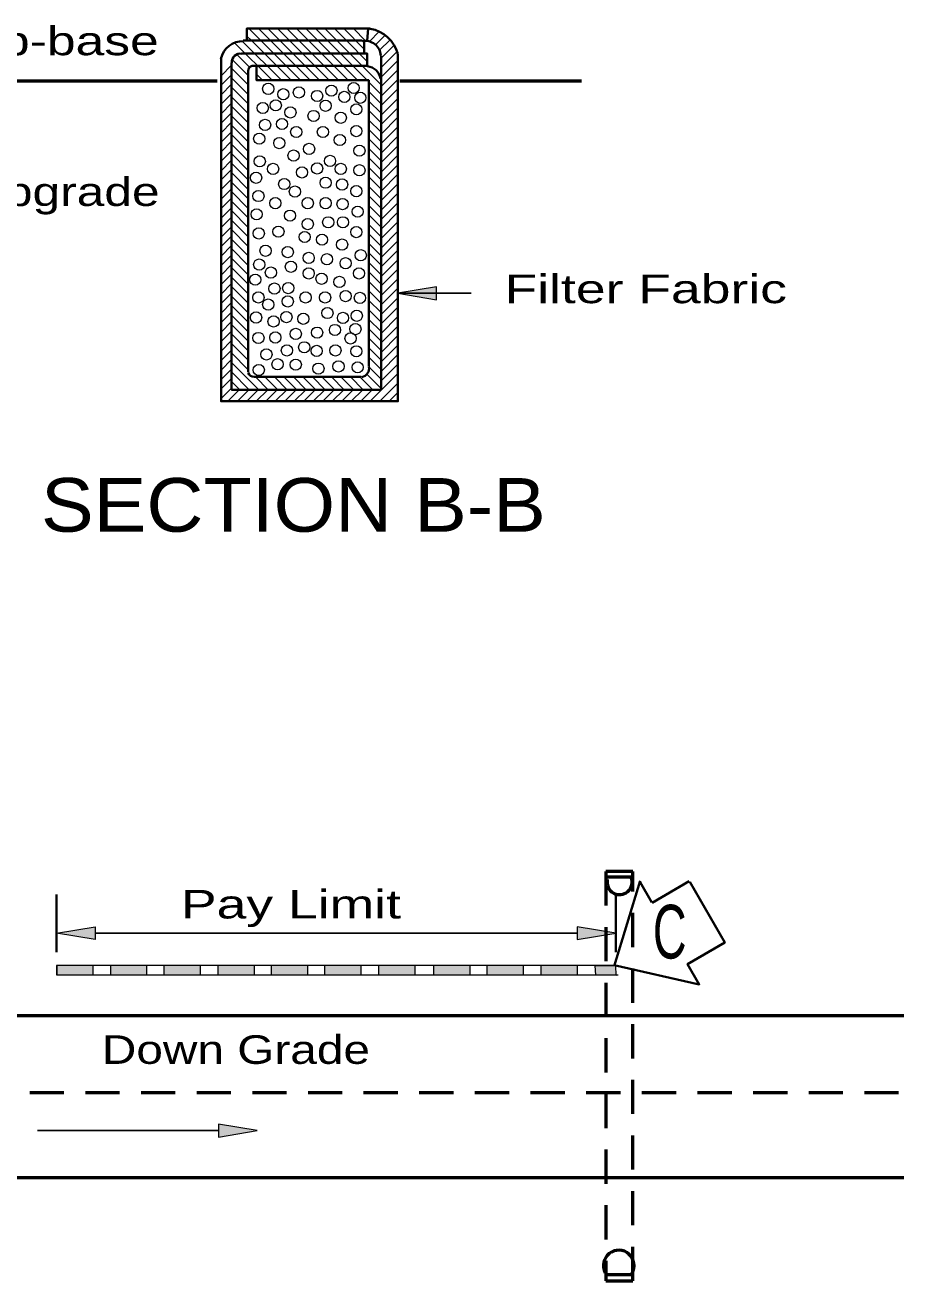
# Model space of a CAD drawing. Extents: x 36 to 71.3, y 0.3 to 22.3.
# Drawn here: x 45.78 to 49.87, y 10.83 to 16.68 of the extents above; entities that cross this region are included whole.
import ezdxf

# ---------------------------------------------------------------- set-up
doc = ezdxf.new("R2010")
doc.units = 0
doc.header["$LTSCALE"] = 0.053
doc.linetypes.add('MEDIUM_DASHED', pattern=[4.5, 3, -1.5])
for name, color, linetype, lineweight in [('1', 7, 'Continuous', 13), ('2', 7, 'Continuous', 13), ('3', 7, 'MEDIUM_DASHED', 53), ('4', 7, 'Continuous', 13)]:
    doc.layers.add(name, color=color, linetype=linetype, lineweight=lineweight)

msp = doc.modelspace()

# ---------------------------------------------------------------- hatches: boundary and pattern name
at = {"layer": '1'}
for points in [[(46.10875, 12.48133), (46.10875, 12.42133), (45.92875, 12.45133), (45.92875, 12.45133)], [(48.35158, 12.48133), (48.35158, 12.42133), (48.53158, 12.45133), (48.53158, 12.45133)], [(45.92875, 12.25708), (46.09933, 12.25708), (46.09933, 12.30033), (45.92875, 12.30033)], [(46.17933, 12.25708), (46.34992, 12.25708), (46.34992, 12.30033), (46.17933, 12.30033)], [(46.42783, 12.25708), (46.59842, 12.25708), (46.59842, 12.30033), (46.42783, 12.30033)], [(46.6795, 12.25708), (46.85008, 12.25708), (46.85008, 12.30033), (46.6795, 12.30033)], [(46.928, 12.25708), (47.09858, 12.25708), (47.09858, 12.30033), (46.928, 12.30033)], [(47.1765, 12.25708), (47.347, 12.25708), (47.347, 12.30033), (47.1765, 12.30033)], [(47.42808, 12.25708), (47.59867, 12.25708), (47.59867, 12.30033), (47.42808, 12.30033)], [(47.68292, 12.25708), (47.8535, 12.25708), (47.8535, 12.30033), (47.68292, 12.30033)], [(47.93142, 12.25708), (48.102, 12.25708), (48.102, 12.30033), (47.93142, 12.30033)], [(48.18308, 12.25708), (48.35358, 12.25708), (48.35358, 12.30033), (48.18308, 12.30033)], [(48.43683, 12.25708), (48.53367, 12.25633), (48.53158, 12.2995), (48.43467, 12.2995)]]:
    msp.add_hatch(color=256, dxfattribs=at).paths.add_polyline_path(points)
at = {"layer": '2'}
for points in [[(47.69758, 15.40008), (47.69758, 15.46008), (47.51758, 15.43008), (47.51758, 15.43008)], [(46.68267, 11.56167), (46.68267, 11.50167), (46.86267, 11.53167), (46.86267, 11.53167)]]:
    msp.add_hatch(color=256, dxfattribs=at).paths.add_polyline_path(points)

# ---------------------------------------------------------------- linework, layer by layer
at = {"layer": '1'}
for p, q in [((46.97633, 16.42192), (46.7935, 16.60475)), ((46.836, 16.6065), (46.8145, 16.628)), ((46.88017, 16.6065), (46.82417, 16.66242)), ((47.0205, 16.42192), (46.836, 16.6065)), ((46.92442, 16.6065), (46.86842, 16.66242)), ((47.06475, 16.42192), (46.88017, 16.6065)), ((46.96858, 16.6065), (46.91258, 16.66242)), ((47.10892, 16.42192), (46.92442, 16.6065)), ((47.01275, 16.6065), (46.95675, 16.66242)), ((47.15308, 16.42192), (46.96858, 16.6065)), ((47.057, 16.6065), (47.001, 16.66242)), ((47.19733, 16.42192), (47.01275, 16.6065)), ((47.10117, 16.6065), (47.04517, 16.66242)), ((47.2415, 16.42192), (47.057, 16.6065)), ((47.14533, 16.6065), (47.08933, 16.66242)), ((47.28567, 16.42192), (47.10117, 16.6065)), ((47.18958, 16.6065), (47.13358, 16.66242)), ((47.32992, 16.42192), (47.14533, 16.6065)), ((47.37408, 16.42192), (47.18958, 16.6065)), ((47.27792, 16.6065), (47.22192, 16.66242)), ((47.36133, 16.56725), (47.26617, 16.66242)), ((47.37525, 16.50917), (47.27792, 16.6065)), ((47.36683, 16.60592), (47.31033, 16.66242)), ((47.38508, 16.60317), (47.4305, 16.64858)), ((47.41358, 16.58742), (47.45808, 16.632)), ((47.43217, 16.56183), (47.48125, 16.61092)), ((46.93217, 16.42192), (46.75742, 16.59667)), ((47.4395, 16.525), (47.50008, 16.58558)), ((47.4395, 16.48075), (47.51417, 16.5555)), ((46.69467, 16.44308), (46.74333, 16.49175)), ((46.82142, 16.44425), (46.74683, 16.51892)), ((46.82733, 16.4825), (46.76758, 16.54233)), ((47.4395, 16.43658), (47.51758, 16.51475)), ((46.69467, 16.39892), (46.74333, 16.4475)), ((46.82142, 16.40008), (46.74333, 16.47817)), ((46.82142, 16.35583), (46.74333, 16.434)), ((46.88792, 16.42192), (46.85967, 16.45025)), ((47.4395, 16.44492), (47.41917, 16.46525)), ((47.4395, 16.39242), (47.51758, 16.4705)), ((46.69467, 16.35475), (46.74333, 16.40333)), ((46.82142, 16.31167), (46.74333, 16.38975)), ((47.4395, 16.3565), (47.38217, 16.41383)), ((47.4395, 16.34817), (47.51758, 16.42633)), ((47.4395, 16.304), (47.51758, 16.38217)), ((46.69467, 16.3105), (46.74333, 16.35917)), ((46.69467, 16.26633), (46.74333, 16.31492)), ((46.82142, 16.2675), (46.74333, 16.34558)), ((47.4395, 16.31233), (47.38217, 16.36958)), ((47.4395, 16.26817), (47.38217, 16.32542)), ((47.4395, 16.25983), (47.51758, 16.33792)), ((46.69467, 16.22217), (46.74333, 16.27075)), ((46.82142, 16.22325), (46.74333, 16.30142)), ((46.82142, 16.17908), (46.74333, 16.25717)), ((47.4395, 16.22392), (47.38217, 16.28125)), ((47.4395, 16.21558), (47.51758, 16.29375)), ((46.69467, 16.17792), (46.74333, 16.22658)), ((46.82142, 16.13492), (46.74333, 16.213)), ((47.4395, 16.17975), (47.38217, 16.237)), ((47.4395, 16.17142), (47.51758, 16.24958)), ((47.4395, 16.12725), (47.51758, 16.20533)), ((46.69467, 16.13375), (46.74333, 16.18233)), ((46.69467, 16.08958), (46.74333, 16.13817)), ((46.82142, 16.09067), (46.74333, 16.16883)), ((47.4395, 16.13558), (47.38217, 16.19283)), ((47.4395, 16.09133), (47.38217, 16.14867)), ((47.4395, 16.083), (47.51758, 16.16117)), ((46.69467, 16.04533), (46.74333, 16.094)), ((46.82142, 16.0465), (46.74333, 16.12458)), ((46.82142, 16.00233), (46.74333, 16.08042)), ((47.4395, 16.04717), (47.38217, 16.10442)), ((47.4395, 16.03883), (47.51758, 16.117)), ((46.69467, 16.00117), (46.74333, 16.04975)), ((46.82142, 15.95808), (46.74333, 16.03625)), ((47.4395, 16.003), (47.38217, 16.06025)), ((47.4395, 15.99467), (47.51758, 16.07275)), ((47.4395, 15.95042), (47.51758, 16.02858)), ((46.69467, 15.95842), (46.74333, 16.007)), ((46.69467, 15.91275), (46.74333, 15.96142)), ((46.82142, 15.91392), (46.74333, 15.992)), ((47.4395, 15.95875), (47.38217, 16.01608)), ((47.4395, 15.91458), (47.38217, 15.97183)), ((47.4395, 15.90625), (47.51758, 15.98442)), ((46.69467, 15.86858), (46.74333, 15.91717)), ((46.82142, 15.86975), (46.74333, 15.94783)), ((46.82142, 15.8255), (46.74333, 15.90367)), ((47.4395, 15.87042), (47.38217, 15.92767)), ((47.4395, 15.86208), (47.51758, 15.94017)), ((46.69467, 15.82442), (46.74333, 15.873)), ((46.82142, 15.78133), (46.74333, 15.85942)), ((47.4395, 15.82617), (47.38217, 15.8835)), ((47.4395, 15.81783), (47.51758, 15.896)), ((47.4395, 15.77367), (47.51758, 15.85183)), ((46.69467, 15.78017), (46.74333, 15.82883)), ((46.82142, 15.73717), (46.74333, 15.81525)), ((47.4395, 15.782), (47.38217, 15.83925)), ((47.4395, 15.73783), (47.38217, 15.79508)), ((47.4395, 15.7295), (47.51758, 15.80758)), ((46.69467, 15.736), (46.74333, 15.78458)), ((46.69467, 15.69183), (46.74333, 15.74042)), ((46.82142, 15.69292), (46.74333, 15.77108)), ((47.4395, 15.69358), (47.38217, 15.75092)), ((47.4395, 15.68533), (47.51758, 15.76342)), ((46.69467, 15.64758), (46.74333, 15.69625)), ((46.82142, 15.64875), (46.74333, 15.72692)), ((46.82142, 15.60458), (46.74333, 15.68267)), ((47.4395, 15.64942), (47.38217, 15.70667)), ((47.4395, 15.64108), (47.51758, 15.71925)), ((47.4395, 15.59692), (47.51758, 15.675)), ((46.69467, 15.60342), (46.74333, 15.652)), ((46.82142, 15.56033), (46.74333, 15.6385)), ((47.4395, 15.60525), (47.38217, 15.6625)), ((47.4395, 15.561), (47.38217, 15.61833)), ((47.4395, 15.55275), (47.51758, 15.63083)), ((46.69467, 15.55925), (46.74333, 15.60783)), ((46.69467, 15.515), (46.74333, 15.56367)), ((46.82142, 15.51617), (46.74333, 15.59433)), ((47.4395, 15.51683), (47.38217, 15.57408)), ((47.4395, 15.5085), (47.51758, 15.58667)), ((46.69467, 15.47083), (46.74333, 15.51942)), ((46.82142, 15.472), (46.74333, 15.55008)), ((46.82142, 15.42775), (46.74333, 15.50592)), ((47.4395, 15.47267), (47.38217, 15.52992)), ((47.4395, 15.46433), (47.51758, 15.54242)), ((47.4395, 15.42017), (47.51758, 15.49825)), ((46.69467, 15.42667), (46.74333, 15.47525)), ((46.82142, 15.38358), (46.74333, 15.46175)), ((47.4395, 15.42842), (47.38217, 15.48575)), ((47.4395, 15.38425), (47.38217, 15.44158)), ((47.4395, 15.37592), (47.51758, 15.45408)), ((46.69467, 15.38242), (46.74333, 15.43108)), ((46.69467, 15.33825), (46.74333, 15.38683)), ((46.82142, 15.33942), (46.74333, 15.4175)), ((47.4395, 15.34008), (47.38217, 15.39733)), ((47.4395, 15.33175), (47.51758, 15.40983)), ((46.69467, 15.29408), (46.74333, 15.34267)), ((46.82142, 15.29517), (46.74333, 15.37333)), ((46.82142, 15.251), (46.74333, 15.32917)), ((47.4395, 15.29583), (47.38217, 15.35317)), ((47.4395, 15.28758), (47.51758, 15.36567)), ((47.4395, 15.24333), (47.51758, 15.3215)), ((46.69467, 15.24983), (46.74333, 15.2985)), ((46.82142, 15.20683), (46.74333, 15.28492)), ((47.4395, 15.25167), (47.38217, 15.309)), ((47.4395, 15.2075), (47.38217, 15.26475)), ((47.4395, 15.19917), (47.51758, 15.27725)), ((46.69467, 15.20567), (46.74333, 15.25425)), ((46.69467, 15.1615), (46.74333, 15.21008)), ((46.82142, 15.16258), (46.74333, 15.24075)), ((47.4395, 15.16325), (47.38217, 15.22058)), ((47.4395, 15.155), (47.51758, 15.23308)), ((46.69467, 15.11725), (46.74333, 15.16592)), ((46.82142, 15.11842), (46.74333, 15.19658)), ((46.82142, 15.07425), (46.74333, 15.15233)), ((47.4395, 15.11908), (47.38217, 15.17642)), ((47.4395, 15.11075), (47.51758, 15.18892)), ((47.4395, 15.06658), (47.51758, 15.14467)), ((46.69467, 15.07308), (46.74333, 15.12167)), ((46.87017, 14.98125), (46.74333, 15.10817)), ((47.4395, 15.07492), (47.38217, 15.13217)), ((47.4395, 15.03067), (47.38342, 15.08675)), ((47.4395, 15.02242), (47.51758, 15.1005)), ((46.69467, 15.02892), (46.74333, 15.0775)), ((46.69467, 14.98467), (46.74333, 15.03333)), ((46.826, 14.98125), (46.74333, 15.064)), ((46.91442, 14.98125), (46.85458, 15.04108)), ((46.95858, 14.98125), (46.89875, 15.04108)), ((47.00275, 14.98125), (46.94292, 15.04108)), ((47.047, 14.98125), (46.98717, 15.04108)), ((47.09117, 14.98125), (47.03133, 15.04108)), ((47.13533, 14.98125), (47.0755, 15.04108)), ((47.17958, 14.98125), (47.11975, 15.04108)), ((47.22375, 14.98125), (47.16392, 15.04108)), ((47.26792, 14.98125), (47.20808, 15.04108)), ((47.31217, 14.98125), (47.25233, 15.04108)), ((47.35633, 14.98125), (47.2965, 15.04108)), ((47.4005, 14.98125), (47.34067, 15.04108)), ((47.4395, 14.9865), (47.37275, 15.05325)), ((47.38908, 14.92783), (47.51758, 15.05633)), ((46.69467, 14.9405), (46.74333, 14.98908)), ((46.72617, 14.92783), (46.77967, 14.98125)), ((46.78183, 14.98125), (46.74333, 15.01975)), ((46.77042, 14.92783), (46.82383, 14.98125)), ((46.81458, 14.92783), (46.86808, 14.98125)), ((46.85875, 14.92783), (46.91225, 14.98125)), ((46.903, 14.92783), (46.95642, 14.98125)), ((46.94717, 14.92783), (47.00067, 14.98125)), ((46.99133, 14.92783), (47.04483, 14.98125)), ((47.03558, 14.92783), (47.089, 14.98125)), ((47.07975, 14.92783), (47.13325, 14.98125)), ((47.12392, 14.92783), (47.17742, 14.98125)), ((47.16817, 14.92783), (47.22158, 14.98125)), ((47.21233, 14.92783), (47.26583, 14.98125)), ((47.2565, 14.92783), (47.31, 14.98125)), ((47.30075, 14.92783), (47.35417, 14.98125)), ((47.34492, 14.92783), (47.39842, 14.98125)), ((47.43333, 14.92783), (47.51758, 15.01208)), ((47.4775, 14.92783), (47.51758, 14.96792)), ((46.18, 12.30092), (46.18, 12.25758))]:
    msp.add_line(p, q, dxfattribs=at)
at = {"layer": '1', "lineweight": 35}
for p, q in [((47.35092, 16.6065), (46.79717, 16.6065)), ((47.36133, 16.54667), (47.36133, 16.60267)), ((46.82142, 15.06275), (46.82142, 16.469)), ((47.3475, 15.04108), (46.84925, 15.04108)), ((48.64517, 12.69467), (48.52425, 12.29808)), ((48.70008, 12.59425), (48.6455, 12.68892)), ((48.87408, 12.6925), (48.701, 12.59258)), ((45.92875, 12.36283), (45.92875, 12.63133)), ((48.53158, 12.362), (48.53158, 12.63133))]:
    msp.add_line(p, q, dxfattribs=at)
at = {"layer": '1', "lineweight": 53}
for p, q in [((45.43675, 16.419), (46.67633, 16.419)), ((47.52742, 16.419), (48.37158, 16.419)), ((48.6105, 12.73867), (48.4855, 12.73867)), ((48.6105, 12.712), (48.4855, 12.712)), ((39.79458, 12.068), (49.87267, 12.068)), ((39.77025, 11.31333), (49.87267, 11.31333)), ((48.6105, 10.86025), (48.4855, 10.86025)), ((48.4855, 10.83225), (48.6105, 10.83225))]:
    msp.add_line(p, q, dxfattribs=at)
at = {"layer": '1', "lineweight": 25}
msp.add_line((46.10875, 12.45133), (48.35158, 12.45133), dxfattribs=at)
at = {"layer": '1', "lineweight": 35}
for points in [[(46.8145, 16.61025), (46.8145, 16.66242), (47.38917, 16.66242)], [(46.79017, 16.54667), (47.37525, 16.54667), (47.37525, 16.48942), (46.84225, 16.48942)], [(46.69467, 16.52117), (46.69467, 14.92783), (47.51758, 14.92783), (47.51758, 16.54283)], [(46.74333, 16.50333), (46.74333, 14.98125), (47.4395, 14.98125), (47.4395, 16.53517)], [(46.85967, 16.48558), (46.85967, 16.42192), (47.38217, 16.42192), (47.38217, 15.09075)], [(48.52358, 12.30192), (48.92058, 12.21233), (48.866, 12.307), (49.03908, 12.40692), (48.87575, 12.68967)]]:
    msp.add_lwpolyline(points, dxfattribs=at)
at = {"layer": '1'}
for points in [[(47.4395, 16.40075), (47.23375, 16.6065), (47.17775, 16.66242)], [(48.52375, 12.30092), (45.93, 12.30092), (45.93, 12.25758), (48.54283, 12.25758)]]:
    msp.add_lwpolyline(points, dxfattribs=at)
for points in [[(46.10875, 12.48133), (46.10875, 12.42133), (45.92875, 12.45133), (45.92875, 12.45133)], [(48.35158, 12.48133), (48.35158, 12.42133), (48.53158, 12.45133), (48.53158, 12.45133)], [(45.92875, 12.25708), (46.09933, 12.25708), (46.09933, 12.30033), (45.92875, 12.30033)], [(46.17933, 12.25708), (46.34992, 12.25708), (46.34992, 12.30033), (46.17933, 12.30033)], [(46.42783, 12.25708), (46.59842, 12.25708), (46.59842, 12.30033), (46.42783, 12.30033)], [(46.6795, 12.25708), (46.85008, 12.25708), (46.85008, 12.30033), (46.6795, 12.30033)], [(46.928, 12.25708), (47.09858, 12.25708), (47.09858, 12.30033), (46.928, 12.30033)], [(47.1765, 12.25708), (47.347, 12.25708), (47.347, 12.30033), (47.1765, 12.30033)], [(47.42808, 12.25708), (47.59867, 12.25708), (47.59867, 12.30033), (47.42808, 12.30033)], [(47.68292, 12.25708), (47.8535, 12.25708), (47.8535, 12.30033), (47.68292, 12.30033)], [(47.93142, 12.25708), (48.102, 12.25708), (48.102, 12.30033), (47.93142, 12.30033)], [(48.18308, 12.25708), (48.35358, 12.25708), (48.35358, 12.30033), (48.18308, 12.30033)], [(48.43683, 12.25708), (48.53367, 12.25633), (48.53158, 12.2995), (48.43467, 12.2995)]]:
    msp.add_lwpolyline(points, close=True, dxfattribs=at)
for centre in [(46.91408, 16.38217), (46.9845, 16.35717), (47.057, 16.36558), (47.14192, 16.349), (47.20817, 16.37375), (47.26833, 16.34483), (47.31175, 16.38617), (46.889, 16.293), (46.94917, 16.30542), (47.18133, 16.30342), (47.32425, 16.28683), (47.34283, 16.34058), (47.01758, 16.27242), (47.12525, 16.25583), (47.25175, 16.24742), (46.8995, 16.21442), (46.97825, 16.21842), (47.0445, 16.18125), (47.16883, 16.18125), (47.32425, 16.18542), (46.8725, 16.15008), (46.96575, 16.12942), (47.2475, 16.14392), (47.03217, 16.0715), (47.10458, 16.1025), (47.33875, 16.09425), (46.87467, 16.0445), (46.93667, 16.00933), (47.14192, 16.01133), (47.20192, 16.0465), (47.25175, 16.00933), (47.33875, 16.00308), (46.85792, 15.96792), (46.98858, 15.93892), (47.0715, 15.99275), (47.18133, 15.94517), (47.25783, 15.93675), (46.86842, 15.883), (47.03825, 15.90375), (47.32425, 15.90575), (46.94717, 15.84983), (47.09833, 15.84983), (47.18133, 15.84983), (47.26008, 15.84575), (46.86017, 15.798), (47.01558, 15.79183), (47.19367, 15.76083), (47.26208, 15.76083), (47.3305, 15.81042), (46.87042, 15.709), (46.96167, 15.71725), (47.09833, 15.75242), (47.32425, 15.71525), (47.08383, 15.69242), (47.16458, 15.68), (47.25783, 15.65725), (46.90158, 15.62825), (47.00508, 15.62208), (47.10258, 15.59508), (47.18742, 15.58892), (47.34483, 15.6075), (46.8725, 15.56408), (46.92642, 15.52675), (47.01967, 15.55367), (47.27442, 15.57025), (46.85392, 15.49358), (47.10258, 15.52267), (47.16258, 15.49775), (47.2455, 15.48333), (47.33658, 15.52267), (46.86842, 15.41075), (46.94292, 15.45217), (47.00717, 15.45433), (47.08808, 15.41075), (47.17908, 15.41075), (47.27442, 15.417), (46.91408, 15.37758), (47.00508, 15.39217), (47.34083, 15.40875), (46.85792, 15.31758), (46.93892, 15.299), (46.99883, 15.31958), (47.07758, 15.31142), (47.18958, 15.33833), (47.26208, 15.31558), (47.32625, 15.32583), (47.04242, 15.241), (47.14192, 15.24717), (47.22475, 15.25958), (47.32, 15.26375), (46.86842, 15.22225), (46.94717, 15.22442), (47.08183, 15.17883), (47.29717, 15.22025), (46.90575, 15.14567), (47.00108, 15.16425), (47.13975, 15.16225), (47.22675, 15.16425), (47.32425, 15.16025), (46.87042, 15.07325), (46.9575, 15.10008), (47.04242, 15.09808), (47.148, 15.0795), (47.24125, 15.08975), (47.3305, 15.08567)]:
    msp.add_circle(centre, 0.02615, dxfattribs=at)
at = {"layer": '1', "lineweight": 35}
for centre, radius, start, end in [((46.79842, 16.49775), 0.10708, 89.97941, 166.81614), ((47.36483, 16.53267), 0.07333, 3.52117, 100.12207), ((47.36092, 16.50192), 0.16229, 15.27318, 80.20162), ((46.78483, 16.50608), 0.04013, 81.25959, 183.23736), ((46.84208, 16.46892), 0.02004, 85.74708, 178.36785), ((47.36567, 16.41583), 0.07286, 11.84876, 81.19348), ((47.33917, 15.08242), 0.04446, 284.22079, 9.4984), ((46.8455, 15.067), 0.02557, 194.64677, 277.64821)]:
    msp.add_arc(centre, radius, start, end, dxfattribs=at)
at = {"layer": '1', "lineweight": 53}
for centre, radius, start, end in [((48.54967, 12.689), 0.0586, 167.41625, 23.05475), ((48.54558, 10.90333), 0.07157, 329.13246, 207.36854)]:
    msp.add_arc(centre, radius, start, end, dxfattribs=at)
at = {"layer": '2', "lineweight": 35}
msp.add_line((47.37508, 16.60525), (47.37975, 16.66242), dxfattribs=at)
at = {"layer": '2', "lineweight": 25}
for p, q in [((47.51758, 15.43008), (47.85883, 15.43008)), ((46.68267, 11.53167), (45.84033, 11.53167))]:
    msp.add_line(p, q, dxfattribs=at)
at = {"layer": '2'}
for points in [[(47.69758, 15.40008), (47.69758, 15.46008), (47.51758, 15.43008), (47.51758, 15.43008)], [(46.68267, 11.56167), (46.68267, 11.50167), (46.86267, 11.53167), (46.86267, 11.53167)]]:
    msp.add_lwpolyline(points, close=True, dxfattribs=at)
at = {"layer": '3'}
for p, q in [((48.4855, 12.73867), (48.4855, 10.83225)), ((48.6105, 10.83225), (48.6105, 12.73867)), ((49.84833, 11.70783), (39.77025, 11.70783))]:
    msp.add_line(p, q, dxfattribs=at)
at = {"layer": '4'}
for p, q in [((48.53158, 12.45133), (48.53167, 12.45133)), ((45.92875, 12.30033), (45.92883, 12.30033)), ((48.53158, 12.2995), (48.53167, 12.2995))]:
    msp.add_line(p, q, dxfattribs=at)

# ---------------------------------------------------------------- texts
at = {"layer": '2'}
for s, height, width, p in [('Sub-base', 0.133, 1.35, (45.37683, 16.53875)), ('Subgrade', 0.133, 1.3, (45.40592, 15.83675)), ('Filter Fabric', 0.133, 1.4, (48.01408, 15.38425)), ('SECTION B-B', 0.25, 1.1, (45.8565, 14.32017)), ('Pay Limit', 0.133, 1.4, (46.50792, 12.51958)), ('C', 0.25, 0.65, (48.70442, 12.33308)), ('Down Grade', 0.133, 1.25, (46.13983, 11.84258))]:
    msp.add_text(s, height=height, dxfattribs=dict(at, width=width)).set_placement(p)

doc.saveas('drawing.dxf')
